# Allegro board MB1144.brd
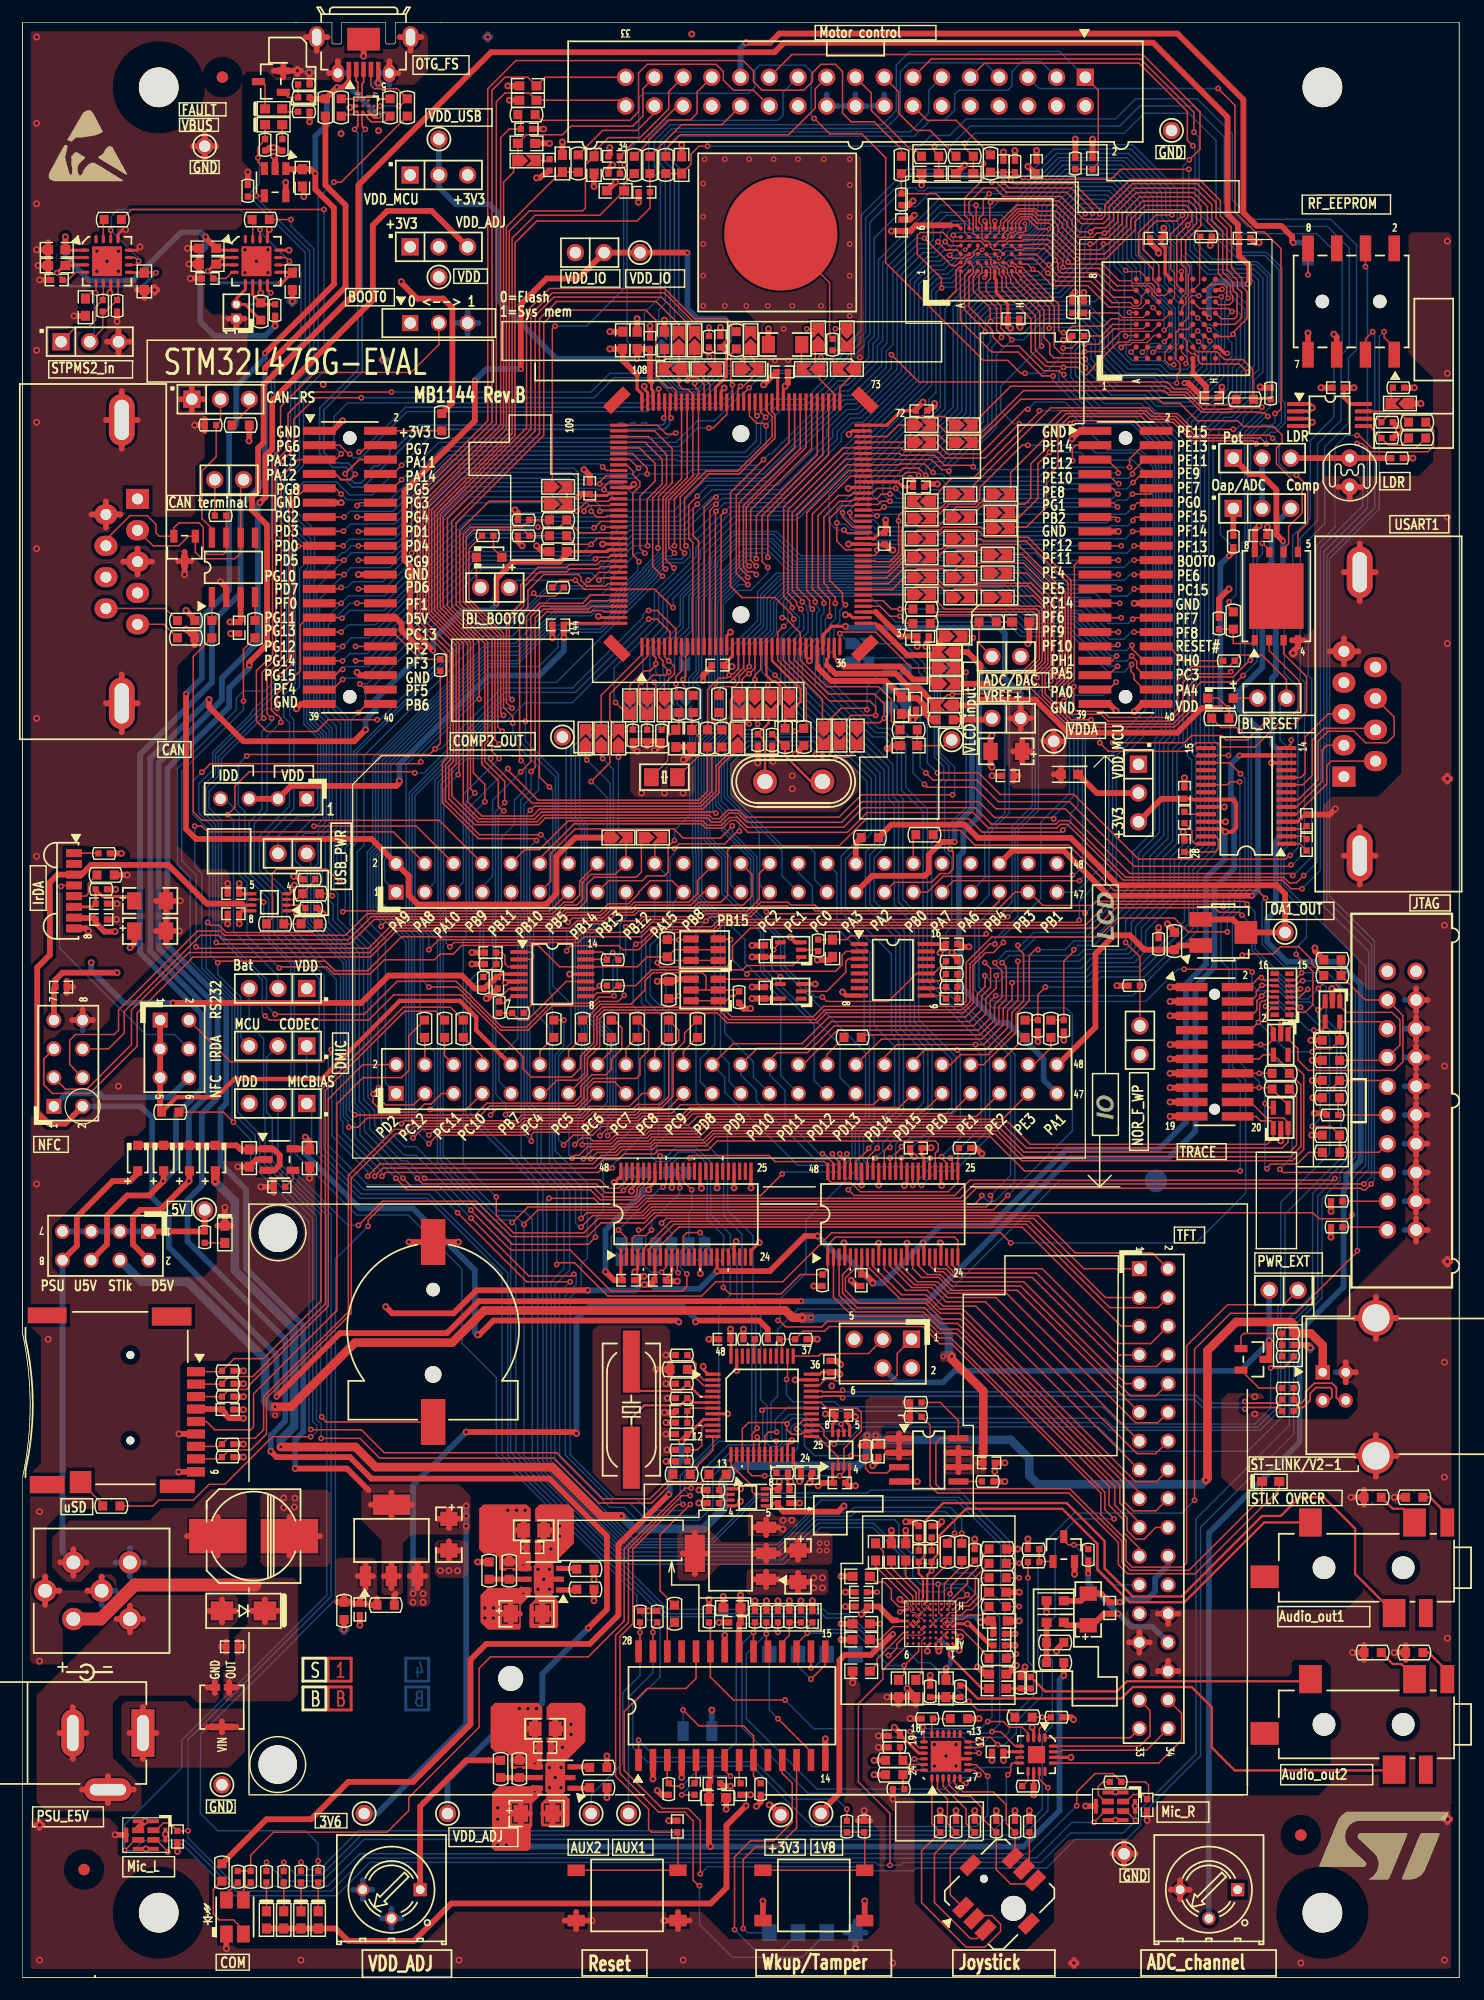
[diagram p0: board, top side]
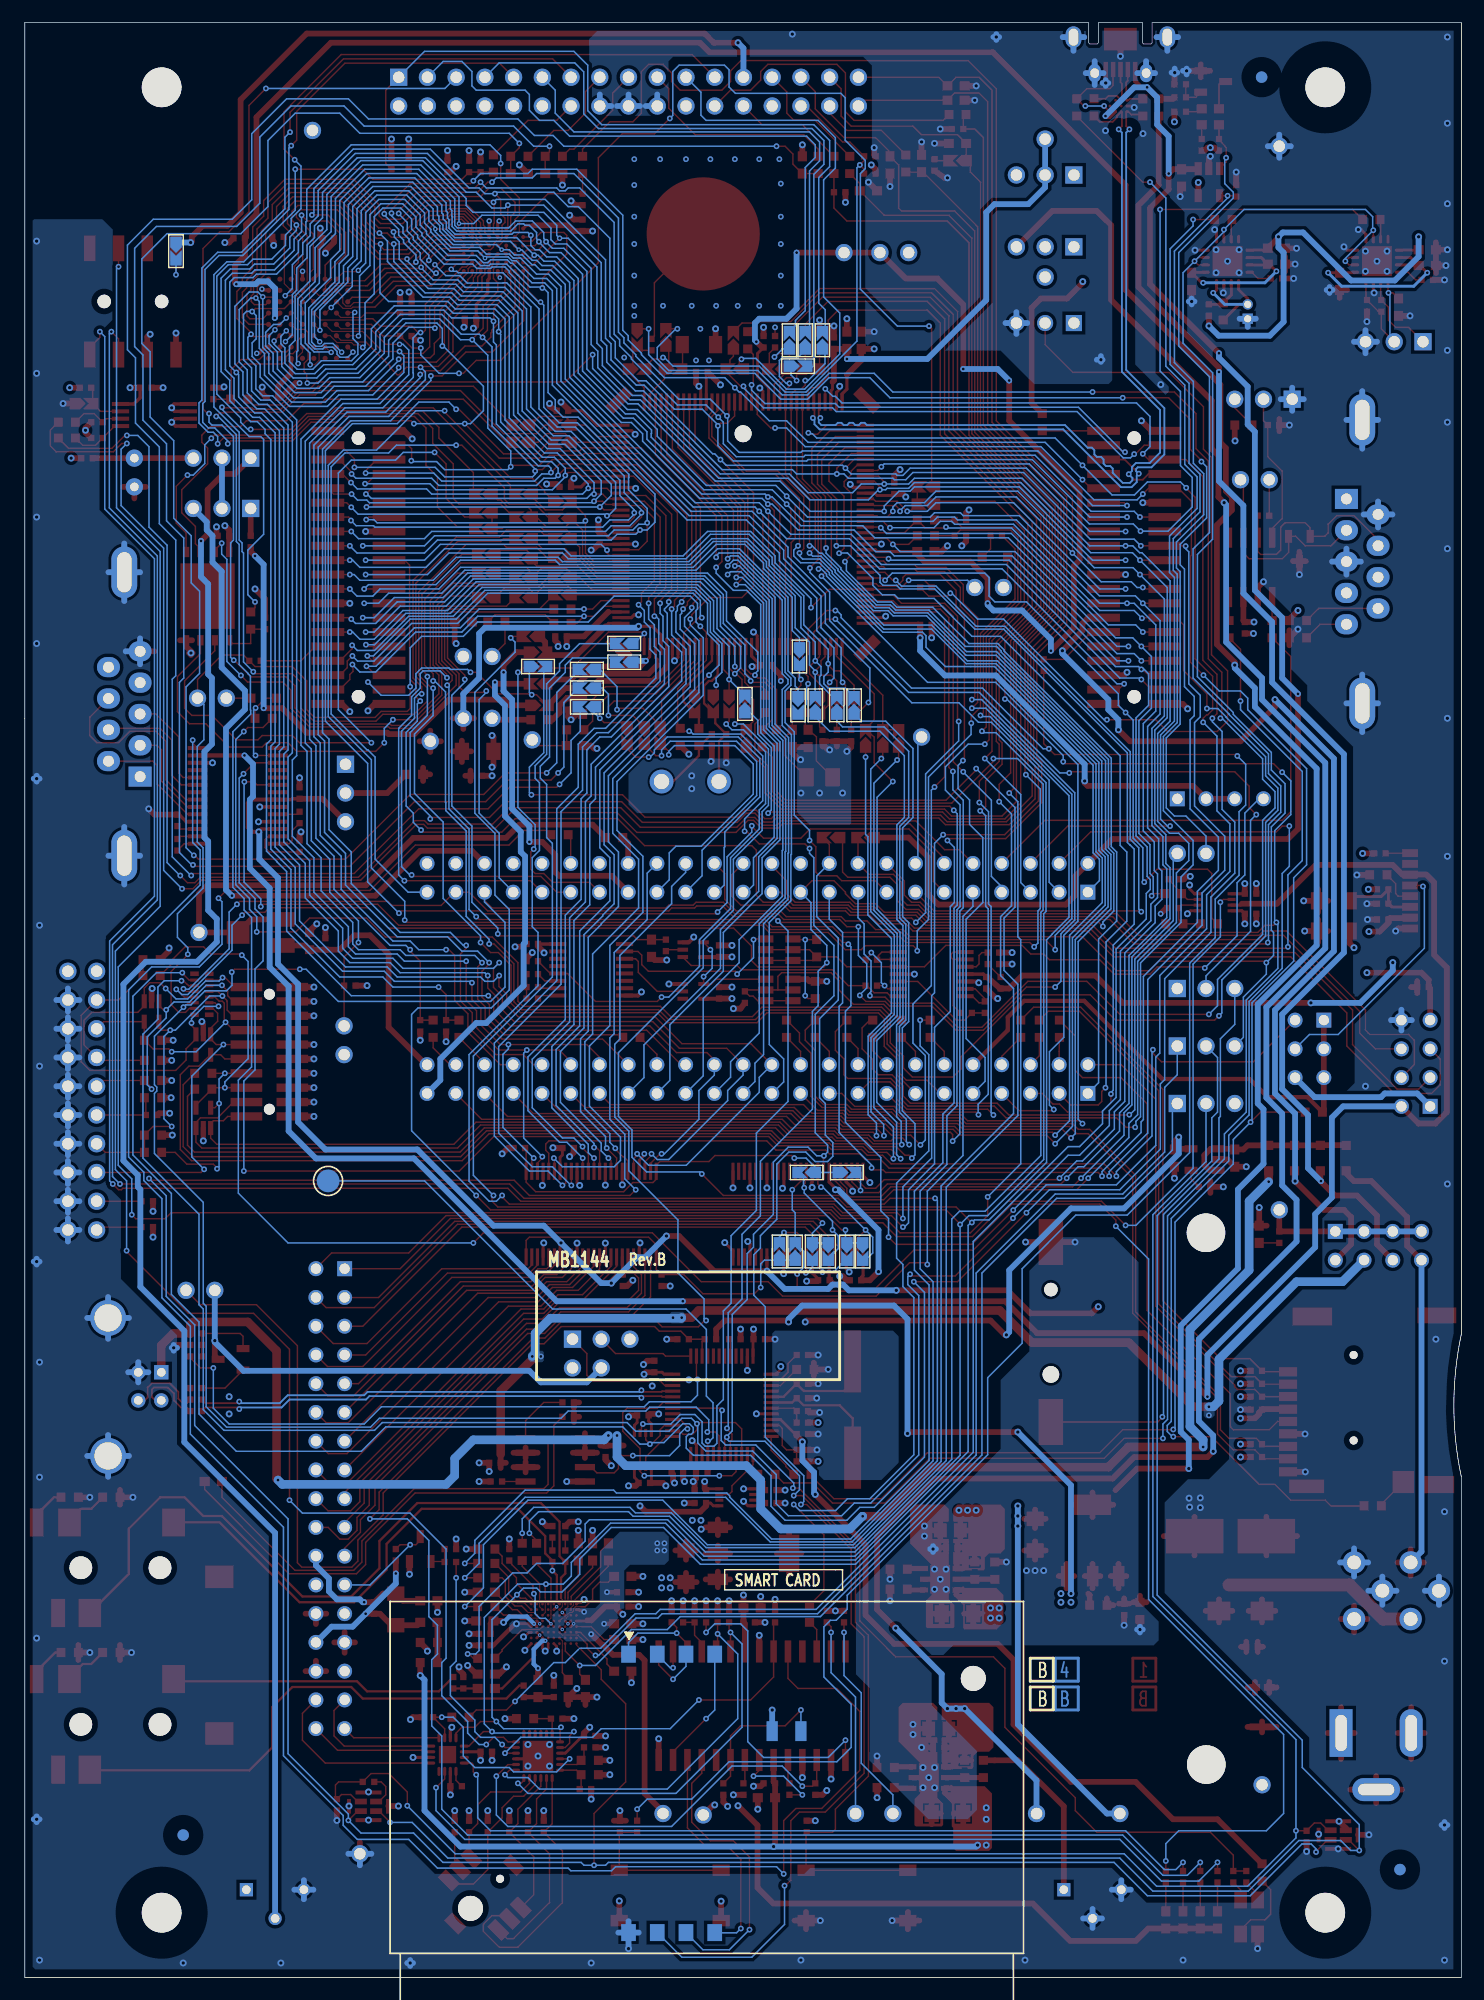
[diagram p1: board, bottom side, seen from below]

Outline 127 x 172.72 mm; copper layers: TOP, L2_VCC, L3_GND, BOTTOM. Coordinates in mm from the lower left corner of the outline.
Outline path: 0,172.72 0,56.87 ; 0,172.72 27.34,172.72 27.34,170.93 27.44,170.83 28.09,170.83 28.19,170.93 28.19,172.72 32.09,172.72 32.09,170.93 32.19,170.83 32.84,170.83 32.94,170.93 32.94,172.72 127,172.72 ; 0,172.72 0,56.87 ; 0,56.87 arc(0.67,50.53) 0,44.2 ; 0,56.87 arc(0.67,50.53) 0,44.2 ; 0,44.2 0,0 ; 0,0 127,0 ; 0,0 127,0 ; 127,0 127,111.25 ; 127,0 127,111.25 ; 127,172.72 127,111.25 ; 127,172.72 127,111.25

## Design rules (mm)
net group DIFFPAIR2: nets PA11 PA12
net group STL_USB: nets STL_USB_DM STL_USB_DP
net group ADDRESS: nets A0 A1 A2 A3 A4 A5 A6 A7 A8 A9 A10 A11 A12 A13 A14 A15 A16 A17 A18 A19 A20 A21 A22 A23
net group DATA: nets D0 D1 D2 D3 D4 D5 D6 D7 D8 D9 D10 D11 D12 D13 D14 D15

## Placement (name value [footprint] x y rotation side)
B1  RESET  [PB10]  53.44 7.24 0 top
B2  WKUP  [PB10]  69.95 7.24 0 top
B3  MT008-A  [MT-008A]  86.33 7.37 315 top
BT1  CR1220 holder  [BAT_2SM_CR1220]  36.29 57.02 90 top
C1  [N_A]  [0603C]  44.67 167.13 0 top
C2  [N_A]  [0603C]  44.67 165.86 0 top
C3  100nF  [0402C]  44.55 163.32 0 top
C4  [N_A]  [0603C]  44.55 162.05 180 top
C5  1nF  [0402C]  52.29 160.91 0 top
C6  [N_A]  [0603C]  47.72 160.27 270 top
C7  1nF  [0402C]  94.58 160.27 270 top
C8  10nF  [0402C]  46.58 160.15 270 top
C9  [N_A]  [0603C]  50.51 160.15 90 top
C10  [N_A]  [0603C]  58.26 160.15 270 top
C11  100nF  [0402C]  86.71 160.02 90 top
C12  100nF  [0402C]  89.63 160.02 90 top
C13  [N_A]  [0603C]  80.23 159.38 0 top
C14  [N_A]  [0603C]  83.28 159.38 0 top
C15  4.7uF  [0603C]  24.73 159 270 top
C16  [N_A]  [0603C]  52.42 157.86 0 top
C17  100nF  [0402C]  54.96 157.73 180 top
C18  100nF  [0402C]  77.69 154.81 90 top
C19  100nF  [0402C]  100.17 153.67 180 top
C20  100nF  [0402C]  108.05 153.67 0 top
C21  1uF  [0603C]  16.35 152.78 180 top
C22  1uF  [0603C]  3.02 152.65 180 top
C23  1uF  [0603C]  16.35 151.38 0 top
C24  1uF  [0603C]  3.02 151.26 0 top
C25  100nF  [0402C]  16.35 150.11 0 top
C26  100nF  [0402C]  3.02 149.99 0 top
C27  1uF  [0603C]  10.76 149.86 270 top
C28  1uF  [0603C]  23.84 149.86 270 top
C29  4.7uF  [0603C]  5.56 147.57 270 top
C30  100nF  [0402C]  93.82 147.57 90 top
C31  100nF  [0402C]  87.6 146.56 0 top
C32  1uF  [0603C]  53.05 144.65 90 top
C33  1uF  [0603C]  54.32 144.65 90 top
C34  220nF  [0603C]  56.74 144.65 270 top
C35  100nF  [0402C]  61.69 144.53 270 top
C36  100nF  [0402C]  55.47 144.4 270 top
C37  22nF(COG)GRM3195C1H223JA01L  [1206C]  67.41 144.27 0 top
C38  100nF  [0402C]  67.15 141.86 180 top
C39  100nF  [0402C]  116.3 140.46 0 top
C40  100nF  [0402C]  105.12 139.57 0 top
C41  100nF  [0402C]  79.47 138.43 180 top
C42  100nF  [0402C]  79.22 131.7 0 top
C43  100nF  [0402C]  50.13 131.57 270 top
C44  100nF  [0402C]  109.44 127.38 0 top
C45  100nF  [0402C]  76.17 127.13 270 top
C46  1uF  [0603C]  47.34 125.98 180 top
C47  [N_A]  [0603C]  88.23 119.76 180 top
C48  100nF  [0402C]  47.34 119.51 0 top
C49  100nF  [0402C]  19.15 119.25 90 top
C50  100nF  [0402C]  79.6 118.49 180 top
C51  100nF  [0402C]  61.44 115.95 0 top
C52  100nF  [0402C]  78.96 112.52 90 top
C53  1uF  [0603C]  77.69 112.39 270 top
C54  20pF  [0402R]  64.99 109.35 270 top
C55  20pF  [0402R]  66.26 109.35 270 top
C56  6pF  [0603C]  57.75 109.47 270 top
C57  6pF  [0603C]  59.15 109.47 270 top
C58  1uF  [0603C]  78.33 108.84 0 top
C59  1uF  [TAN-A]  86.96 108.33 0 top
C60  100nF  [0402C]  87.09 106.17 0 top
C61  100nF  [0402C]  102.71 104.65 270 top
C62  100nF  [0402C]  102.71 102.49 270 top
C63  100nF  [0402C]  113.51 102.23 90 top
C64  100nF  [0402C]  113.51 100.08 90 top
C65  100nF  [0402C]  102.71 99.95 90 top
C66  100nF  [0402C]  18.64 95.76 0 top
C67  4.7uF  [TAN-A]  11.27 95.12 180 top
C68  100nF  [0402C]  6.95 94.87 180 top
C69  100nF  [0402C]  18.64 93.98 0 top
C70  100nF  [0402C]  6.95 93.47 180 top
C71  4.7uF  [TAN-A]  11.27 92.46 180 top
C72  100nF  [0402C]  82.14 91.31 0 top
C73  1uF  [0603C]  71.6 90.93 270 top
C74  100nF  [0402C]  65.63 90.68 270 top
C75  100nF  [0402C]  42.01 87.88 270 top
C76  100nF  [0402C]  65.63 87 90 top
C77  1nF  [0402C]  82.14 86.49 0 top
C78  100nF  [0402C]  3.4 87.5 180 top
C79  100nF  [0402C]  78.96 73.28 180 top
C80  1uF  [0603C]  20.03 72.39 270 top
C81  1uF  [0603C]  25.37 72.39 270 top
C82  10nF  [0402C]  22.7 69.85 180 top
C83  100nF  [0402C]  53.56 61.59 0 top
C84  100nF  [0402C]  56.36 61.59 0 top
C85  100nF  [0402C]  74.14 61.59 270 top
C86  100nF  [0402C]  62.07 56.39 0 top
C87  100nF  [0402C]  71.34 53.98 90 top
C88  20pF  [0402R]  58.26 52.45 0 top
C89  20pF  [0402R]  58.26 51.18 0 top
C90  100nF  [0402C]  18.13 50.16 0 top
C91  100nF  [0402C]  58.26 50.04 0 top
C92  100nF  [0402C]  72.36 49.66 0 top
C93  100nF  [0402C]  58.26 48.01 0 top
C94  100nF  [0402C]  69.31 44.58 180 top
C95  100nF  [0402C]  72.23 43.69 180 top
C96  100nF  [0402C]  67.28 43.05 0 top
C97  100nF  [0402C]  67.28 41.91 0 top
C98  10uF[ESR<0.2ohm]  [0805C]  45.18 39.5 0 top
C99  10uF  [TAN-A]  37.69 39.12 90 top
C100  220uF  [C310M-6]  20.42 38.99 180 top
C101  100nF  [0402C]  45.05 37.97 0 top
C102  2.2uF  [0603C]  75.41 37.59 270 top
C103  2.2uF  [0603C]  76.8 37.59 90 top
C104  2.2uF  [0603C]  78.07 37.59 90 top
C105  100nF  [0402C]  79.22 37.21 90 top
C106  100nF  [0402C]  80.36 37.21 90 top
C107  10uF  [TAN-A]  68.55 36.32 90 top
C108  1uF  [0603C]  74.14 35.43 180 top
C109  100nF  [0402C]  74.14 34.04 180 top
C110  1uF  [0603C]  86.2 34.04 0 top
C111  100nF  [0402C]  74.14 32.77 180 top
C112  4.7uF  [0603C]  62.71 32.64 180 top
C113  100nF  [0402C]  96.11 32.64 270 top
C114  100nF  [0402C]  29.81 32.51 270 top
C115  10uF  [TAN-A]  94.2 32.51 270 top
C116  4.7uF  [TAN-A]  44.55 32.13 180 top
C117  100nF  [0402C]  69.82 31.88 270 top
C118  1uF  [0603C]  86.33 31.5 0 top
C119  100nF  [0402C]  62.96 31.37 180 top
C120  4.7uF  [0603C]  74.14 31.24 180 top
C121  100nF  [0402C]  86.33 30.35 0 top
C122  4.7uF  [0603C]  74.14 29.84 180 top
C123  100nF  [0402C]  86.33 29.34 0 top
C124  100nF  [0402C]  18.51 29.21 180 top
C125  4.7uF  [0603C]  74.14 27.05 0 top
C126  4.7uF  [0603C]  86.2 26.8 0 top
C127  4.7uF  [0603C]  77.44 25.53 90 top
C128  4.7uF  [0603C]  78.96 25.53 90 top
C129  4.7uF  [0603C]  81.63 25.53 90 top
C130  4.7uF  [0603C]  86.2 25.53 180 top
C131  10uF[ESR<0.2ohm]  [0805C]  46.2 21.97 0 top
C132  100nF  [0402C]  77.06 21.34 180 top
C133  100nF  [0402C]  46.2 20.32 0 top
C134  100nF  [0402C]  86.2 19.94 180 top
C135  100nF  [0402C]  61.18 17.14 0 top
C136  100nF  [0402C]  59.4 16.64 90 top
C137  100nF  [0402C]  63.47 16.64 270 top
C138  4.7uF  [0603C]  61.44 15.88 0 top
C139  100nF  [0402C]  99.41 15.24 270 top
C140  4.7uF  [TAN-A]  45.43 14.48 180 top
C141  100nF  [0402C]  57.88 13.34 270 top
C142  100nF  [0402C]  13.68 12.45 270 top
C143  100nF  [0402C]  85.44 45.47 180 top
C144  100nF  [0402C]  41.37 90.55 180 top
C145  100nF  [0402C]  75.66 46.48 270 top
CN1  475900001  [MOLEX_47590001]  30.14 168.58 180 top
CN2  MC_connector  [IDC34S]  93.95 167.89 270 top
CN3  F206A-2_04MGF-A  [SSM-104-L-DH]  117.44 148.08 0 top
CN4  Header 3X1  [SIP3]  3.4 144.53 0 top
CN5  DB9-male  [DB9_M]  10.16 125.09 90 top
CN6  P1039-2_20MGF-089-1A  [FTR-120-53-L-D-LC]  28.92 124.59 270 top
CN7  P1039-2_20MGF-089-1A  [FTR-120-53-L-D-LC]  97.5 124.59 270 top
CN8  Header 2X1  [SIP2]  88.23 116.71 180 top
CN9  DB9-male  [DB9_M]  116.81 111.63 270 top
CN10  -  [SIP2]  85.69 111.25 0 top
CN11  Header 24X2  [HDR_2X24_2R54]  33.02 95.89 0 top
CN12  -  [FTSH-110-01-L-DV]  105.38 81.79 270 top
CN13  female conn 4X2  [HDR_2X4_2R54_N]  2.76 76.96 90 top
CN14  Header 24X2  [HDR_2X24_2R54]  33.02 78.11 0 top
CN15  JTAG  [IDC20S]  120.65 88.9 0 top
CN16  [N_A]  [HDR_2X3-1_2R54-6]  78.58 56.39 180 top
CN17  USB-typeB connector  [USB-B]  114.94 53.47 90 top
CN18  PJS008-2000 (SMS064FF or SMS128FF)  [MSD_PJS008_]  9.53 54.99 270 top
CN19  16-bit connector  [HDR_2X17_2R54]  98.72 62.62 270 top
CN20  PJ3028B-3  [PJ3028B]  122.05 36.2 180 top
CN21  PJ3028B-3  [PJ3028B]  122.05 22.35 180 top
CN22  DC-10B  [PWR_JACK_DC10]  10.64 21.59 0 top
CN23  C816  [SAM_C816]  69.82 16.26 270 bottom
D1  EMIF02-USB03F2  [BGA11_0R5_1R57X2R07]  30.32 165.35 270 top
D2  ESDCAN24-2BLY  [SOT23-213]  14.32 126.24 180 top
D3  BAT60JFILM  [SOD-323]  41.24 125.48 180 top
D4  BAT60JFILM  [SOD-323]  105.89 113.03 180 top
D5  BAT60JFILM  [SOD-323]  10.18 72.39 90 top
D6  BAT60JFILM  [SOD-323]  12.47 72.39 90 top
D7  BAT60JFILM  [SOD-323]  14.75 72.39 90 top
D8  BAT60JFILM  [SOD-323]  17.04 72.39 90 top
JP1  -  [SIP3]  34.26 159.26 0 top
JP2  -  [SIP3]  34.26 152.91 0 top
JP3  -  [SIP2]  48.86 152.4 0 top
JP4  -  [SIP3]  14.95 139.45 0 top
JP5  -  [SIP3]  107.03 134.24 0 top
JP6  -  [SIP2]  16.99 132.33 0 top
JP7  -  [SIP3]  107.03 129.79 0 top
JP8  -  [SIP2]  43.02 122.81 180 top
JP9  -  [SIP2]  111.73 113.03 180 top
JP10  -  [SIP3]  98.65 107.19 270 top
JP11  Header 4  [SIP4]  25.11 104.14 180 top
JP12  -  [SIP3]  25.11 87.38 180 top
JP13  -  [SIP2]  98.77 81.53 90 top
JP14  -  [SIP3]  25.11 82.3 180 top
JP15  Header 3X2  [HDR_2X3_2R54]  12.16 84.58 270 top
JP16  -  [SIP3]  25.11 77.22 180 top
JP17  Header 4X2  [HDR_2X4_2R54]  11.14 65.91 180 top
JP18  -  [SIP2]  110.2 60.71 0 top
JP19  -  [SIP2]  25.11 99.31 180 top
L1  BEAD  [0603L]  92.55 106.3 180 top
L2  BNX002-01  [BNX001]  6.98 34.16 180 top
L3  BEAD  [0603L]  91.28 33.27 180 top
L4  BEAD  [0603L]  91.28 31.37 180 top
LD1  Green  [0603D]  26.13 5.08 90 top
LD2  Orange  [0603D]  24.61 5.08 90 top
LD3  Red  [0603D]  23.08 5.08 90 top
LD4  Blue  [0603D]  21.56 5.08 90 top
LD5  Green  [0603D]  22.19 165.1 180 top
LD6  Red  [0603D]  22.19 163.7 180 top
LD7  Red  [0603D]  17.88 65.66 90 top
LD8  HSMF-A201-A00J1  [LED2_3528]  18.76 5.33 0 top
LD9  Red  [0603D]  110.33 43.81 180 top
NOREF  -  [unnamed]  12.03 5.71 0 top
NOREF#2  -  [#2]  239.8 163.12 0 top
NOREF#3  -  [#2]  6.32 0 0 top
NOREF#4  -  [unnamed]  5.43 9.53 0 top
NOREF#5  -  [#2]  12.67 209.55 0 top
NOREF#6  -  [#2]  139.03 -25.03 90 top
NOREF#7  -  [#2]  0 172.72 0 top
NOREF#8  -  [unnamed]  114.9 167 0 top
NOREF#9  -  [unnamed]  12.03 167 0 top
NOREF#10  -  [unnamed]  113 12.57 0 top
NOREF#11  -  [unnamed]  114.9 5.71 0 top
NOREF#12  -  [#2]  5.81 -7.11 0 top
NOREF#13  -  [#2]  141.57 -25.03 90 top
NOREF#14  -  [#2]  402.05 -43.74 0 top
NOREF#15  -  [#2]  127 0 90 top
NOREF#16  -  [unnamed]  17.66 167.9 0 top
NOREF#17  -  [#2]  176.5 202.69 0 top
NOREF#18  -  [unnamed]  113 12.57 180 bottom
NOREF#19  -  [unnamed]  5.43 9.53 180 bottom
NOREF#20  -  [unnamed]  17.66 167.9 180 bottom
NOREF#21  -  [unnamed]  22.58 65.79 180 bottom
NOREF#22  -  [unnamed]  22.55 18.8 180 bottom
R1  47K  [0402R]  24.86 166.12 180 top
R2  0  [0603R]  26.77 165.23 90 top
R3  0  [0603R]  28.16 165.23 270 top
R4  0  [0603R]  32.48 165.23 270 top
R5  0  [0603R]  34 165.23 270 top
R6  330  [0402R]  24.86 164.85 180 top
R7  0  [0603R]  44.55 164.59 180 top
R8  47K  [0402R]  21.43 161.93 90 top
R9  620  [0402R]  22.96 161.93 90 top
R10  0  [0603R]  80.23 160.91 180 top
R11  0  [0603R]  83.28 160.91 180 top
R12  0  [0603R]  49.12 160.27 270 top
R13  0  [0603R]  85.57 160.27 270 top
R14  3K3  [0402R]  93.06 160.27 90 top
R15  0  [0603R]  54.07 160.15 90 top
R16  0  [0603R]  55.47 160.15 270 top
R17  0  [0603R]  56.86 160.15 90 top
R18  0  [0603R]  77.69 160.15 90 top
R19  100K  [0402R]  87.73 160.02 90 top
R20  3K3  [0402R]  52.29 159.38 180 top
R21  10K  [0402R]  19.91 157.86 270 top
R22  10K  [0402R]  77.69 157.1 90 top
R23  0  [0603R]  7.97 155.32 180 top
R24  0  [0603R]  21.05 155.32 180 top
R25  10K  [0402R]  104.62 153.8 180 top
R26  1K  [0402R]  7.08 147.7 270 top
R27  1K  [0402R]  8.35 147.7 270 top
R28  10K  [0402R]  92.81 147.57 270 top
R29  3K3  [0402R]  22.32 147.32 90 top
R30  PT100  [HDR_1X2_1R27]  18.89 146.56 90 top
R31  100 1%  [0603R]  21.05 147.19 270 top
R32  10K  [0402R]  93.31 145.03 0 top
R33  0  [SB_0603]  58.01 144.65 270 top
R34  0  [0603R]  63.09 144.65 270 top
R35  0  [SB_0603]  64.36 144.65 270 top
R36  0  [SB_0603]  59.4 144.65 270 top
R37  1K  [0402R]  60.67 144.53 90 top
R38  0  [SB_0603]  70.33 144.91 270 top
R39  0  [SB_0603]  72.87 144.91 90 top
R40  10K  [0402R]  71.6 144.27 90 top
R41  10K  [0402R]  110.33 139.95 270 top
R42  10K  [0402R]  121.63 140.46 180 top
R43  0  [0603R]  108.05 139.45 180 top
R44  0  [0603R]  37.05 137.41 270 top
R45  10K  [0402R]  16.61 137.16 180 top
R46  0  [0603R]  19.27 137.16 0 top
R48  0  [SB_0603]  79.47 137.16 180 top
R50  0  [SB_0603]  79.47 135.64 180 top
R51  8.2K  [0402R]  121.51 134.24 0 top
R52  VT9ON1  [PVT901]  117.32 132.97 180 top
R53  0  [SB_0603]  47.34 130.18 180 top
R54  0  [SB_0603]  79.47 130.43 0 top
R55  120  [0402R]  17.49 129.16 180 top
R56  0  [SB_0603]  79.47 128.91 180 top
R57  1K2  [0402R]  44.29 128.78 180 top
R58  0  [0603R]  47.34 128.78 0 top
R59  150  [0402R]  41.12 127.38 180 top
R60  1K2  [0402R]  44.29 127.38 180 top
R61  0  [0603R]  47.34 127.38 0 top
R62  0  [SB_0603]  79.47 127.13 180 top
R63  1K  [0402R]  107.03 126.87 270 top
R64  0  [SB_0603]  79.47 125.48 180 top
R65  0  [SB_0603]  82.9 125.35 180 top
R66  0  [SB_0603]  79.47 123.7 180 top
R67  10K  [0402R]  47.34 122.81 0 top
R68  0  [SB_0603]  79.47 122.17 180 top
R69  0  [0603R]  79.47 120.9 0 top
R70  [N_A]  [0603R]  14.45 119.89 180 top
R71  0  [0603R]  107.03 119.89 90 top
R72  0  [0603R]  85.31 119.76 180 top
R73  0  [0603R]  79.47 119.63 0 top
R74  10K  [0402R]  105.76 119.63 270 top
R75  0  [0603R]  16.73 119.13 270 top
R76  0  [0603R]  20.54 119.13 90 top
R77  0  [0603R]  14.45 118.36 180 top
R78  0  [SB_0603]  81.63 117.09 0 top
R79  820  [0402R]  106.65 116.33 180 top
R80  820  [0402R]  36.93 115.95 270 top
R81  0  [SB_0603]  81.63 115.7 180 top
R82  0  [SB_0603]  81.63 114.3 180 top
R83  0  [SB_0603]  81.5 112.39 0 top
R84  0  [SB_0603]  53.69 112.39 90 top
R85  0  [SB_0603]  55.21 112.39 90 top
R86  0  [SB_0603]  56.74 112.39 90 top
R87  0  [0603R]  58.01 112.52 90 top
R88  0  [0603R]  59.28 112.52 90 top
R89  0  [0603R]  61.56 112.52 90 top
R90  0  [SB_0603]  63.34 112.52 90 top
R91  0  [SB_0603]  64.74 112.52 90 top
R92  0  [0603R]  81.5 111.12 180 top
R93  0  [0603R]  105.89 111.25 180 top
R94  0  [0603R]  78.33 110.24 0 top
R95  390  [0603R]  67.41 109.6 270 top
R96  [N_A]  [0603R]  69.06 109.6 270 top
R97  0  [SB_0603]  70.83 109.73 90 top
R98  0  [SB_0603]  72.23 109.73 90 top
R99  0  [SB_0603]  73.76 109.73 90 top
R100  100K  [0402R]  53.94 109.73 270 top
R101  100K  [0402R]  55.21 109.73 270 top
R102  100K  [0402R]  56.48 109.73 270 top
R103  0  [SB_0603]  51.15 109.47 270 top
R104  0  [SB_0603]  52.67 109.47 270 top
R105  0  [0603R]  60.55 109.47 90 top
R106  0  [0603R]  61.82 109.47 90 top
R107  0  [0603R]  79.72 100.97 180 top
R108  0  [SB_0603]  52.67 100.71 180 top
R109  0  [SB_0603]  55.72 100.71 180 top
R110  100K  [0402R]  78.96 50.8 0 top
R111  0  [0603R]  74.9 100.71 180 top
R112  5.1  [0402R]  7.21 99.31 180 top
R113  0  [0603R]  7.33 97.41 0 top
R114  100K  [0402R]  25.37 97.03 180 top
R115  47  [0402R]  6.95 96.14 180 top
R116  0  [0603R]  25.5 95.76 0 top
R117  100K  [0402R]  25.5 94.49 0 top
R118  0  [0603R]  22.32 93.09 180 top
R119  [N_A]  [0603R]  25.37 93.09 0 top
R120  [N_A]  [0603R]  101.82 91.57 90 top
R121  1K  [0402R]  100.43 91.31 270 top
R122  10K  [0402R]  70.33 91.19 90 top
R123  1K[1%]  [0603R]  56.99 90.93 90 top
R124  1K  [0402R]  41.37 89.53 180 top
R125  3K6 0.1%  [0402R]  52.17 89.92 0 top
R126  [N_A]  [0603R]  115.79 89.92 180 top
R127  220K  [0402R]  82.14 89.79 180 top
R128  22K  [0402R]  40.74 87.88 90 top
R129  180K 0.1%  [0402R]  43.78 85.22 0 top
R130  30K  [0402R]  82.14 88.65 0 top
R131  [N_A]  [0603R]  115.79 88.52 0 top
R132  180K 0.1%  [0402R]  52.17 87.63 0 top
R133  10K  [0402R]  98.27 87.63 0 top
R134  15K  [0402R]  82.14 87.5 0 top
R135  1[1%]  [0603R]  57.12 87.25 90 top
R136  3K6 0.1%  [0402R]  42.13 85.72 270 top
R137  220K  [0402R]  63.34 86.61 270 top
R138  100K  [0402R]  89.76 84.07 270 top
R139  100K  [0402R]  92.04 84.07 270 top
R140  0  [0603R]  35.53 83.82 270 top
R141  0  [0603R]  37.31 83.82 270 top
R142  0  [0603R]  38.96 83.82 270 top
R143  0  [0603R]  46.96 83.82 270 top
R144  0  [0603R]  49.5 83.82 270 top
R145  0  [0603R]  52.04 83.82 270 top
R146  0  [0603R]  54.32 83.82 270 top
R147  0  [0603R]  57.12 83.82 270 top
R148  0  [0603R]  59.66 83.82 270 top
R149  0  [0603R]  88.61 83.82 270 top
R150  0  [0603R]  90.9 83.82 270 top
R151  0  [0603R]  73.37 83.06 180 top
R152  [N_A]  [0603R]  115.67 82.8 180 top
R153  [N_A]  [0603R]  115.67 81.03 180 top
R154  0  [0603R]  111.22 79.88 0 top
R155  [N_A]  [0603R]  115.67 79.25 0 top
R156  0  [0603R]  111.22 78.49 0 top
R157  [N_A]  [0603R]  115.67 77.72 180 top
R158  [N_A]  [0603R]  13.05 76.45 0 top
R159  10K  [0402R]  115.79 76.2 0 top
R160  [N_A]  [0603R]  115.67 74.42 180 top
R161  10K  [0402R]  83.28 73.28 180 top
R162  [N_A]  [0603R]  115.67 72.9 0 top
R163  10K  [0402R]  116.17 68.58 0 top
R164  10K  [0402R]  116.17 66.29 0 top
R165  1K  [0402R]  16.1 65.41 90 top
R166  10K  [0402R]  70.71 61.59 90 top
R167  10K  [0402R]  111.86 56.9 180 top
R168  100K  [0402R]  64.23 56.39 180 top
R169  2K2  [0402R]  66.39 56.39 180 top
R170  4K7  [0402R]  68.8 56.39 180 top
R171  36K  [0402R]  111.86 55.88 0 top
R172  10K  [0402R]  58.26 54.99 0 top
R173  100  [0402R]  111.86 54.86 180 top
R174  [N_A]  [0603R]  58.01 53.72 0 top
R175  47K  [0402R]  18.13 53.59 180 top
R176  47K  [0402R]  18.13 52.45 180 top
R177  1.5K  [0402R]  111.86 52.07 0 top
R178  47K  [0402R]  18.13 51.31 180 top
R179  22  [0402R]  111.86 51.05 0 top
R180  22  [0402R]  111.86 50.04 0 top
R181  100K  [0402R]  58.26 49.02 180 top
R182  47K  [0402R]  18.13 47.12 180 top
R183  4K7  [0402R]  58.26 46.61 180 top
R184  2K2  [0402R]  85.31 43.81 0 top
R185  47K  [0402R]  18.13 45.97 180 top
R186  4K7  [0402R]  58.26 45.59 0 top
R187  100K  [0402R]  67.15 44.58 0 top
R188  0  [0603R]  58.26 44.45 180 top
R189  0  [0603R]  61.44 44.45 0 top
R190  100K  [0402R]  61.06 43.05 0 top
R191  0  [0603R]  119.35 42.42 180 top
R192  0  [0603R]  123.03 42.42 0 top
R193  100K  [0402R]  61.06 41.91 0 top
R194  0  [0603R]  7.84 41.66 180 top
R195  20  [0402R]  79.22 39.37 90 top
R196  20  [0402R]  80.36 39.37 90 top
R197  [N_A]  [0603R]  86.2 37.85 180 top
R198  0  [0603R]  81.76 37.59 90 top
R199  0  [0603R]  83.03 37.59 90 top
R200  10K  [0402R]  84.17 37.34 90 top
R201  0  [0603R]  86.2 36.58 0 top
R202  [N_A]  [0603R]  49.75 36.07 180 top
R203  11.8K[1%]  [0603R]  41.24 35.94 90 top
R204  20.5K[1%]  [0603R]  43.02 35.94 270 top
R205  0  [0603R]  86.2 35.31 0 top
R206  [N_A]  [0603R]  49.75 34.29 0 top
R207  124[1%]  [0603R]  32.1 32.89 0 top
R208  0  [0603R]  86.2 32.77 0 top
R209  232[1%]  [0603R]  28.42 32.38 90 top
R210  0  [0603R]  57.63 32.13 90 top
R211  10K  [0402R]  54.58 31.88 270 top
R212  10K  [0402R]  56.1 31.88 270 top
R213  100K  [0402R]  60.67 31.88 90 top
R214  100K  [0402R]  64.74 31.88 270 top
R215  100K  [0402R]  65.75 31.88 270 top
R216  4K7  [0402R]  66.77 31.88 270 top
R217  10K  [0402R]  67.79 31.88 270 top
R218  10K  [0402R]  68.8 31.88 90 top
R219  [N_A]  [0603R]  91.28 29.59 180 top
R220  0  [0603R]  119.35 28.7 180 top
R221  0  [0603R]  123.03 28.7 180 top
R222  0  [0603R]  86.2 28.19 180 top
R223  0  [0603R]  91.28 27.81 180 top
R224  1K  [0402R]  88.23 26.04 270 top
R225  180  [0402R]  89.12 26.04 90 top
R226  1K  [0402R]  80.23 25.27 270 top
R227  180  [0402R]  82.9 25.27 270 top
R228  0  [0603R]  88.49 22.99 0 top
R229  100K  [0402R]  91.41 22.99 180 top
R230  10K  [0402R]  79.98 22.86 0 top
R231  [N_A]  [0603R]  82.77 22.86 180 top
R232  10K  [0402R]  77.06 20.32 0 top
R233  [N_A]  [0603R]  77.06 19.18 0 top
R234  [N_A]  [0603R]  50.9 18.54 180 top
R235  10.2K[1%]  [0603R]  42.26 18.41 90 top
R236  20K[1%]  [0603R]  43.91 18.41 270 top
R237  [N_A]  [0603R]  77.06 17.91 0 top
R238  10K  [0402R]  96.62 17.27 0 top
R239  100K  [0402R]  88.87 16.89 0 top
R240  [N_A]  [0603R]  50.9 16.76 0 top
R241  100K  [0402R]  57.12 16.64 270 top
R242  100K  [0402R]  65.25 16.64 90 top
R243  10K  [0402R]  77.44 16.64 0 top
R244  330  [0402R]  72.87 13.34 90 top
R245  220K  [0402R]  74.39 13.34 90 top
R246  10K  [0402R]  81.12 13.34 270 top
R247  10K  [0402R]  82.52 13.34 90 top
R248  10K  [0402R]  84.17 13.34 90 top
R249  10K  [0402R]  86.07 13.34 90 top
R250  10K  [0402R]  87.73 13.34 90 top
R251  100  [0402R]  89 13.34 270 top
R252  0  [0603R]  17.62 9.27 90 top
R253  100  [0402R]  19.02 8.89 270 top
R254  100  [0402R]  20.16 8.89 270 top
R255  680  [0402R]  21.56 8.89 270 top
R256  680  [0402R]  23.08 8.89 270 top
R257  680  [0402R]  24.61 8.89 270 top
R258  510  [0402R]  26.13 8.89 270 top
R259  47K  [0402R]  94.2 37.34 90 top
R260  1K  [0402R]  89.38 36.7 0 top
R261  22K  [0402R]  24.86 167.26 180 top
R262  10K  [0402R]  74.52 46.48 90 top
R263  1K2  [0402R]  120.62 136.02 180 top
R264  1K2  [0402R]  120.62 137.41 180 top
R265  0  [0603R]  123.29 136.02 0 top
R266  0  [0603R]  123.29 137.41 0 top
R267  22K  [0402R]  89.38 37.85 180 top
R268  1K  [0402R]  78.96 49.53 0 top
RS1  22  [RP0402X8_REV]  111.22 87 90 top
RV1  3386P-503H[5%]  [3386P]  32.61 7.75 180 top
RV2  3314J-1-103  [PTF_3314J]  106.14 92.33 270 top
RV3  3386P-103(10K)  [3386P]  104.87 7.75 180 top
SB1  Open by default  [SB_0603]  44.55 160.53 180 top
SB2  Open by default  [SB_0603]  60.55 142.11 180 top
SB3  Open by default  [SB_0603]  72.87 142.11 0 top
SB4  Open by default  [SB_0603]  57.5 142.11 0 top
SB5  Open by default  [SB_0603]  64.23 142.11 180 top
SB6  Open by default  [SB_0603]  69.69 142.11 0 top
SB7  Closed by default  [SB_0603]  121.76 139.06 0 top
SB8  Open by default  [SB_0603]  83.15 137.16 180 top
SB9  Open by default  [SB_0603]  83.15 135.64 180 top
SB10  Open by default  [SB_0603]  47.34 131.7 180 top
SB11  Open by default  [SB_0603]  82.9 131.06 180 top
SB12  Open by default  [SB_0603]  86.46 131.06 180 top
SB13  Open by default  [SB_0603]  82.9 129.03 180 top
SB14  Open by default  [SB_0603]  86.46 129.41 180 top
SB15  Open by default  [SB_0603]  86.46 128.02 180 top
SB16  Open by default  [SB_0603]  82.9 127.13 180 top
SB17  Open by default  [SB_0603]  86.2 125.73 180 top
SB18  Open by default  [SB_0603]  86.2 124.08 180 top
SB19  Open by default  [SB_0603]  82.9 123.7 180 top
SB20  Open by default  [SB_0603]  86.2 121.92 180 top
SB21  Open by default  [SB_0603]  82.9 121.92 180 top
SB22  Open by default  [SB_0603]  82.26 118.49 180 top
SB23  Open by default  [SB_0603]  67.79 112.52 90 top
SB24  Open by default  [SB_0603]  66.14 112.52 90 top
SB25  Open by default  [SB_0603]  63.21 109.47 270 top
SB26  Open by default  [SB_0603]  49.75 109.47 270 top
SB27  Open by default  [SB_0603]  59.4 144.65 270 bottom
SB28  Open by default  [SB_0603]  58.01 144.65 270 bottom
SB29  Open by default  [SB_0603]  56.48 144.65 270 bottom
SB30  Open by default  [SB_0603]  58.64 142.37 0 bottom
SB31  Open by default  [SB_0603]  74.01 117.86 180 bottom
SB32  Open by default  [SB_0603]  74.01 116.2 180 bottom
SB33  Open by default  [SB_0603]  58.52 116.71 90 bottom
SB34  Open by default  [SB_0603]  77.31 115.57 180 bottom
SB35  Open by default  [SB_0603]  81.63 115.82 0 bottom
SB36  Open by default  [SB_0603]  77.31 113.92 180 bottom
SB37  Open by default  [SB_0603]  63.34 112.52 270 bottom
SB38  Open by default  [SB_0603]  57.12 112.39 270 bottom
SB39  Open by default  [SB_0603]  55.21 112.39 270 bottom
SB40  Open by default  [SB_0603]  53.69 112.39 270 bottom
SB41  Open by default  [SB_0603]  58.64 112.39 90 bottom
SB42  Open by default  [SB_0603]  77.31 112.27 180 bottom
SB43  Open by default  [SB_0603]  113.63 152.53 90 bottom
SB44  Open by default  [SB_0603]  52.93 64.14 90 bottom
SB45  Closed by default  [SB_0603]  54.32 64.14 90 bottom
SB46  Open by default  [SB_0603]  55.98 64.14 90 bottom
SB47  Closed by default  [SB_0603]  57.37 64.14 90 bottom
SB48  Closed by default  [SB_0603]  57.88 71.12 180 bottom
SB49  Open by default  [SB_0603]  54.32 71.12 0 bottom
SB50  Closed by default  [SB_0603]  60.29 64.14 270 bottom
SB51  Open by default  [SB_0603]  58.9 64.14 270 bottom
SW1  09.03290.01  [SW1_3TH_2R54_10X2R5]  34.26 146.18 0 top
T1  9013-SOT23  [SOT-23]  21.94 167.51 90 top
T2  FDC606P  [SOT23-6]  60.29 90.81 90 top
T3  FDC606P  [SOT23-6]  60.29 87.25 90 top
T4  9013-SOT23  [SOT-23]  108.81 54.61 270 top
T6  9013-SOT23  [SOT-23]  92.04 37.85 0 top
TP1  [N_A]  [TP]  101.57 163.19 180 top
TP2  [N_A]  [TP]  36.8 162.43 0 top
TP3  [N_A]  [TP]  16.1 161.8 270 top
TP4  [N_A]  [TP]  54.58 152.4 0 top
TP5  [N_A]  [TP]  36.8 150.24 0 top
TP6  [N_A]  [TP]  47.72 109.6 180 top
TP7  [N_A]  [TP]  82.14 109.35 0 top
TP8  [N_A]  [TP]  91.15 109.22 90 top
TP9  [N_A]  [TP]  111.6 92.33 270 top
TP10  [N_A]  [TP]  16.1 67.82 180 top
TP11  [N_A]  [TP]  17.62 17.02 180 top
TP12  [N_A]  [TP]  30.19 14.48 90 top
TP13  [N_A]  [TP]  37.56 14.48 180 top
TP14  [N_A]  [TP]  50.26 14.48 0 top
TP15  [N_A]  [TP]  53.56 14.48 0 top
TP16  [N_A]  [TP]  70.58 14.48 180 top
TP17  [N_A]  [TP]  67.02 14.35 180 top
TP18  [N_A]  [TP]  97.38 10.92 0 top
TP19  [N_A]  [TP_C79]  100.19 70.37 180 bottom
TS1  -  [TS_PAD]  67.02 154.05 0 top
U1  STMPS2151STR  [SOT23-5]  22.32 158.62 180 top
U2  IS61WV102416BLL-10MLI  [BGA48_0R75_9X11]  85.57 152.65 90 top
U3  STPMS2L-PUR  [QFN16_0R65_4X4]  7.46 151.64 0 top
U4  STPMS2L-PUR  [QFN16_0R65_4X4]  20.67 151.64 0 top
U5  M29W128GL70ZA6E  [BGA64_1_10X13]  101.95 146.56 90 top
U6  M24128-DFDW6TP  [TSSOP8_0R65_3X6R4]  115.54 138.05 270 top
U7  STM32L476ZGT6U  [TQFP144_0R5_22X22_SOCKET]  63.5 128.4 90 top
U8  SN65HVD230  [SOIC8_1R27_4R9X6]  18.64 124.59 0 top
U9  N25Q256A13EF840E  [DFN8_1R27_6X8_TP4R8X5R8]  110.84 122.05 0 top
U10  ST3241EBPR  [SSOP28_0R65_10R2X7R8]  108.17 104.39 90 top
U11  TFDU6300  [IR_VISHAY3]  4.54 96.01 90 top
U12  SN74LVC2T45DCUT  [USOP8_0R5_2X3R1]  21.81 95 90 top
U13  SN74LVC1G66DCKT  [SC70-5]  67.91 90.81 90 top
U14  74LV4060PW  [TSSOP16_0R65_5X6R4]  76.93 89.03 270 top
U15  TSZ124IPT  [TSSOP14_0R65_5X6R4]  46.83 88.65 270 top
U16  SN74LVC1G04DCKT  [SC70-5]  67.91 87.12 90 top
U17  ESDALC6V1W5  [SOT-353]  115.79 85.34 180 top
U18  ESDALC6V1W5  [SOT-353]  111.22 82.42 180 top
U19  ESDALC6V1W5  [SOT-353]  111.22 75.95 0 top
U20  LD3985M33R  [SOT23-5]  22.7 72.26 270 top
U21  SN74LVC16T245DGGR  [TSSOP48_0R5_12R5X8R1]  58.64 67.44 0 top
U22  SN74LVC16T245DGGR  [TSSOP48_0R5_12R5X8R1]  76.93 67.44 0 top
U23  STM32F103CBT6  [LQFP48_0R5_9X9]  65.37 50.55 0 top
U24  SN74LVC2T45DCUT  [USOP8_0R5_2X3R1]  72.36 46.61 0 top
U25  SN74LVC2T45DCUT  [USOP8_0R5_2X3R1]  64.1 42.42 270 top
U26  LD1117STR  [SOT-223]  32.61 38.61 0 top
U27  LD1117S18TR  [SOT-223]  62.58 37.47 90 top
U28  ST1L05BPUR  [DFN6_0R95_3X3]  46.07 35.18 90 top
U29  WM8994ECS_R  [BGA72_0R5_4R5X4]  80.23 31.24 180 top
U30  ST8024CDR  [SOIC28W_1R27_17R9X10R325]  62.71 24 0 top
U31  ZEN056V130A24LS  [TYCO_ZEN056V130A24LS]  17.62 23.88 90 top
U32  STMPE811QTR  [QFN16_0R5_3X3]  89.63 19.68 270 top
U33  STMPE1600QTR  [QFN24_0R5_4X4]  81.63 19.56 90 top
U34  ST1L05BPUR  [DFN6_0R95_3X3]  47.09 17.65 90 top
U35  -  [MP34DT01TR]  96.62 15.11 270 top
U36  -  [MP34DT01TR]  10.89 12.57 270 top
U37  ST890CDR  [SOIC8_1R27_4R9X6]  80.11 45.72 270 top
X1  NDK NX3215SA-32.768K-STD-MUA-14  [XTAL_2SM_3R2X1R5]  56.74 106.05 180 top
X2  8MHz (with socket)  [XTAL_SOCKET]  70.71 105.66 0 top
X3  8MHz  [XTAL_2SM_12R7X4R7]  53.82 50.16 90 top
Z1  SMAJ5.0A-TR  [SMA]  19.53 32.38 0 top

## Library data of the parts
B1 B2 = PB10
B3 = MT-008A
BT1 = BAT_2SM_CR1220
C1 C2 C4 C6 C9 C10 C13-C16 C21-C24 C27-C29 C32-C34 C46 C47 C53 C56-C58 C73 C80 C81 C102-C104 C108 C110 C112 C118 C120 C122 C125-C130 C138 = 0603C
C3 C5 C7 C8 C11 C12 C17-C20 C25 C26 C30 C31 C35 C36 C38-C45 C48-C52 C60-C66 C68-C70 C72 C74-C79 C82-C87 C90-C97 C101 C105 C106 C109 C111 C113 C114 C117 C119 C121 C123 C124 C132-C137 C139 C141-C145 = 0402C
C37 = 1206C
C54 C55 C88 C89 R1 R6 R8 R9 R14 R19-R22 R25-R29 R32 R37 R40-R42 R45 R51 R55 R57 R59 R60 R63 R67 R74 R79 R80 R100-R102 R110 R112 R114 R115 R117 R121 R122 R124 R125 R127-R130 R132-R134 R136-R139 R159 R161 R163-R173 R175-R187 R190 R193 R195 R196 R200 R211-R218 R224-R227 R229 R230 R232 R238 R239 R241-R251 R253-R264 R267 R268 = 0402R
C59 C67 C71 C99 C107 C115 C116 C140 = TAN-A
C98 C131 = 0805C
C100 = C310M-6
CN1 = MOLEX_47590001
CN2 = IDC34S
CN3 = SSM-104-L-DH
CN4 JP1 JP2 JP4 JP5 JP7 JP10 JP12 JP14 JP16 = SIP3
CN5 CN9 = DB9_M
CN6 CN7 = FTR-120-53-L-D-LC
CN8 CN10 JP3 JP6 JP8 JP9 JP13 JP18 JP19 = SIP2
CN11 CN14 = HDR_2X24_2R54
CN12 = FTSH-110-01-L-DV
CN13 = HDR_2X4_2R54_N
CN15 = IDC20S
CN16 = HDR_2X3-1_2R54-6
CN17 = USB-B
CN18 = MSD_PJS008_
CN19 = HDR_2X17_2R54
CN20 CN21 = PJ3028B
CN22 = PWR_JACK_DC10
CN23 = SAM_C816
D1 = BGA11_0R5_1R57X2R07
D2 = SOT23-213
D3-D8 = SOD-323
JP11 = SIP4
JP15 = HDR_2X3_2R54
JP17 = HDR_2X4_2R54
L1 L3 L4 = 0603L
L2 = BNX001
LD1-LD7 LD9 = 0603D
LD8 = LED2_3528
R2-R5 R7 R10-R13 R15-R18 R23 R24 R31 R34 R43 R44 R46 R58 R61 R69-R73 R75-R77 R87-R89 R92-R96 R105-R107 R111 R113 R116 R118-R120 R123 R126 R131 R135 R140-R158 R160 R162 R174 R188 R189 R191 R192 R194 R197-R199 R201-R210 R219-R223 R228 R231 R233-R237 R240 R252 R265 R266 = 0603R
R30 = HDR_1X2_1R27
R33 R35 R36 R38 R39 R48 R50 R53 R54 R56 R62 R64-R66 R68 R78 R81-R86 R90 R91 R97-R99 R103 R104 R108 R109 SB1-SB51 = SB_0603
R52 = PVT901
RS1 = RP0402X8_REV
RV1 RV3 = 3386P
RV2 = PTF_3314J
SW1 = SW1_3TH_2R54_10X2R5
T1 T4 T6 = SOT-23
T2 T3 = SOT23-6
TP1-TP18 = TP
TP19 = TP_C79
TS1 = TS_PAD
U1 U20 = SOT23-5
U2 = BGA48_0R75_9X11
U3 U4 = QFN16_0R65_4X4
U5 = BGA64_1_10X13
U6 = TSSOP8_0R65_3X6R4
U7 = TQFP144_0R5_22X22_SOCKET
U8 U37 = SOIC8_1R27_4R9X6
U9 = DFN8_1R27_6X8_TP4R8X5R8
U10 = SSOP28_0R65_10R2X7R8
U11 = IR_VISHAY3
U12 U24 U25 = USOP8_0R5_2X3R1
U13 U16 = SC70-5
U14 = TSSOP16_0R65_5X6R4
U15 = TSSOP14_0R65_5X6R4
U17-U19 = SOT-353
U21 U22 = TSSOP48_0R5_12R5X8R1
U23 = LQFP48_0R5_9X9
U26 U27 = SOT-223
U28 U34 = DFN6_0R95_3X3
U29 = BGA72_0R5_4R5X4
U30 = SOIC28W_1R27_17R9X10R325
U31 = TYCO_ZEN056V130A24LS
U32 = QFN16_0R5_3X3
U33 = QFN24_0R5_4X4
U35 U36 = MP34DT01TR
X1 = XTAL_2SM_3R2X1R5
X2 = XTAL_SOCKET
X3 = XTAL_2SM_12R7X4R7
Z1 = SMA

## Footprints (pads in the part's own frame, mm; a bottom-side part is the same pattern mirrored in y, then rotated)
0402C
  rect 0.559x0.559 smd: 1(-0.508,0) 2(0.508,0)
0402R
  rect 0.559x0.559 smd: 1(-0.508,0) 2(0.508,0)
0603C
  rect 0.889x0.813 smd: 1(-0.762,0) 2(0.762,0)
0603D
  rect 0.889x0.813 smd: 1(-0.762,0) 2(0.762,0)
0603L
  rect 0.889x0.813 smd: 1(-0.762,0) 2(0.762,0)
0603R
  rect 0.787x0.813 smd: 1(-0.762,0) 2(0.762,0)
0805C
  rect 1.143x1.27 smd: 1(-0.889,0) 2(0.889,0)
1206C
  rect 1.168x1.524 smd: 1(-1.473,0) 2(1.473,0)
3386P
  rect 1.168x1.168 hole 0.762: 1(-2.54,0)
  round 1.168 hole 0.762: 2(0,2.54) 3(2.54,0)
BAT_2SM_CR1220
  round 1.473 hole 1.473 unplated: (-3.75,0)
  round 1.194 hole 1.194 unplated: (3.75,0)
  rect 4.064x2.159 smd: 1(-7.95,0) 2(7.95,0)
BGA11_0R5_1R57X2R07
  round 0.249 smd: A2(0,0.75) A3(0.5,0.75) B1(-0.5,0.25) B2(0,0.25) B3(0.5,0.25) C1(-0.5,-0.25) C2(0,-0.25) C3(0.5,-0.25) D1(-0.5,-0.75) D2(0,-0.75) D3(0.5,-0.75)
BGA48_0R75_9X11
  round 0.356 smd: A1(-1.875,2.625) A2(-1.125,2.625) A3(-0.375,2.625) A4(0.375,2.625) A5(1.125,2.625) A6(1.875,2.625) B1(-1.875,1.875) B2(-1.125,1.875) B3(-0.375,1.875) B4(0.375,1.875) B5(1.125,1.875) B6(1.875,1.875) C1(-1.875,1.125) C2(-1.125,1.125) C3(-0.375,1.125) C4(0.375,1.125) C5(1.125,1.125) C6(1.875,1.125) D1(-1.875,0.375) D2(-1.125,0.375) D3(-0.375,0.375) D4(0.375,0.375) D5(1.125,0.375) D6(1.875,0.375) E1(-1.875,-0.375) E2(-1.125,-0.375) E3(-0.375,-0.375) E4(0.375,-0.375) E5(1.125,-0.375) E6(1.875,-0.375) F1(-1.875,-1.125) F2(-1.125,-1.125) F3(-0.375,-1.125) F4(0.375,-1.125) F5(1.125,-1.125) F6(1.875,-1.125) G1(-1.875,-1.875) G2(-1.125,-1.875) G3(-0.375,-1.875) G4(0.375,-1.875) G5(1.125,-1.875) G6(1.875,-1.875) H1(-1.875,-2.625) H2(-1.125,-2.625) H3(-0.375,-2.625) H4(0.375,-2.625) H5(1.125,-2.625) H6(1.875,-2.625)
BGA64_1_10X13
  round 0.457 smd: A1(-3.5,3.5) A2(-2.5,3.5) A3(-1.5,3.5) A4(-0.5,3.5) A5(0.5,3.5) A6(1.5,3.5) A7(2.5,3.5) A8(3.5,3.5) B1(-3.5,2.5) B2(-2.5,2.5) B3(-1.5,2.5) B4(-0.5,2.5) B5(0.5,2.5) B6(1.5,2.5) B7(2.5,2.5) B8(3.5,2.5) C1(-3.5,1.5) C2(-2.5,1.5) C3(-1.5,1.5) C4(-0.5,1.5) C5(0.5,1.5) C6(1.5,1.5) C7(2.5,1.5) C8(3.5,1.5) D1(-3.5,0.5) D2(-2.5,0.5) D3(-1.5,0.5) D4(-0.5,0.5) D5(0.5,0.5) D6(1.5,0.5) D7(2.5,0.5) D8(3.5,0.5) E1(-3.5,-0.5) E2(-2.5,-0.5) E3(-1.5,-0.5) E4(-0.5,-0.5) E5(0.5,-0.5) E6(1.5,-0.5) E7(2.5,-0.5) E8(3.5,-0.5) F1(-3.5,-1.5) F2(-2.5,-1.5) F3(-1.5,-1.5) F4(-0.5,-1.5) F5(0.5,-1.5) F6(1.5,-1.5) F7(2.5,-1.5) F8(3.5,-1.5) G1(-3.5,-2.5) G2(-2.5,-2.5) G3(-1.5,-2.5) G4(-0.5,-2.5) G5(0.5,-2.5) G6(1.5,-2.5) G7(2.5,-2.5) G8(3.5,-2.5) H1(-3.5,-3.5) H2(-2.5,-3.5) H3(-1.5,-3.5) H4(-0.5,-3.5) H5(0.5,-3.5) H6(1.5,-3.5) H7(2.5,-3.5) H8(3.5,-3.5)
BGA72_0R5_4R5X4
  round 0.249 smd: A1(-2,1.75) A2(-1.5,1.75) A3(-1,1.75) A4(-0.5,1.75) A5(0,1.75) A6(0.5,1.75) A7(1,1.75) A8(1.5,1.75) A9(2,1.75) B1(-2,1.25) B2(-1.5,1.25) B3(-1,1.25) B4(-0.5,1.25) B5(0,1.25) B6(0.5,1.25) B7(1,1.25) B8(1.5,1.25) B9(2,1.25) C1(-2,0.75) C2(-1.5,0.75) C3(-1,0.75) C4(-0.5,0.75) C5(0,0.75) C6(0.5,0.75) C7(1,0.75) C8(1.5,0.75) C9(2,0.75) D1(-2,0.25) D2(-1.5,0.25) D3(-1,0.25) D4(-0.5,0.25) D5(0,0.25) D6(0.5,0.25) D7(1,0.25) D8(1.5,0.25) D9(2,0.25) E1(-2,-0.25) E2(-1.5,-0.25) E3(-1,-0.25) E4(-0.5,-0.25) E5(0,-0.25) E6(0.5,-0.25) E7(1,-0.25) E8(1.5,-0.25) E9(2,-0.25) F1(-2,-0.75) F2(-1.5,-0.75) F3(-1,-0.75) F4(-0.5,-0.75) F5(0,-0.75) F6(0.5,-0.75) F7(1,-0.75) F8(1.5,-0.75) F9(2,-0.75) G1(-2,-1.25) G2(-1.5,-1.25) G3(-1,-1.25) G4(-0.5,-1.25) G5(0,-1.25) G6(0.5,-1.25) G7(1,-1.25) G8(1.5,-1.25) G9(2,-1.25) H1(-2,-1.75) H2(-1.5,-1.75) H3(-1,-1.75) H4(-0.5,-1.75) H5(0,-1.75) H6(0.5,-1.75) H7(1,-1.75) H8(1.5,-1.75) H9(2,-1.75)
BNX001
  round 1.981 hole 1.219: 1(2.5,2.5) 2(-2.5,2.5) 3(2.5,-2.5) 4(0,0) 5(5,0) 6(-2.5,-2.5)
C310M-6
  rect 5.08x3.048 smd: 1(3.175,0) 2(-3.175,0)
DB9_M
  rect 1.778x2.032 hole 0.965: 1(5.537,0)
  oval 1.778x2.032 hole 0.965: 2(2.769,0) 3(0,0) 4(-2.769,0) 5(-5.537,0) 6(4.166,2.794) 7(1.397,2.794) 8(-1.372,2.794) 9(-4.14,2.794)
  oval 4.572x2.286 hole 3.556x1.27: 10(-12.522,1.397) 11(12.522,1.397)
DFN6_0R95_3X3
  rect 0.457x0.711 smd: 1(-0.95,-1.436) 2(0,-1.436) 3(0.95,-1.436) 4(0.95,1.436) 5(0,1.436) 6(-0.95,1.436)
  rect 2.515x1.753 smd: 7(0,0)
DFN8_1R27_6X8_TP4R8X5R8
  rect 0.559x0.914 smd: 1(-1.905,-3.9) 2(-0.635,-3.9) 3(0.635,-3.9) 4(1.905,-3.9) 5(1.905,3.9) 6(0.635,3.9) 7(-0.635,3.9) 8(-1.905,3.9)
  rect 4.801x5.791 smd: 9(0,0)
FTR-120-53-L-D-LC
  round 1.194 hole 1.194 unplated: (-11.43,0) (11.43,0)
  rect 0.711x2.896 smd: 1(-12.065,-2.705) 2(-12.065,2.705) 3(-10.795,-2.705) 4(-10.795,2.705) 5(-9.525,-2.705) 6(-9.525,2.705) 7(-8.255,-2.705) 8(-8.255,2.705) 9(-6.985,-2.705) 10(-6.985,2.705) 11(-5.715,-2.705) 12(-5.715,2.705) 13(-4.445,-2.705) 14(-4.445,2.705) 15(-3.175,-2.705) 16(-3.175,2.705) 17(-1.905,-2.705) 18(-1.905,2.705) 19(-0.635,-2.705) 20(-0.635,2.705) 21(0.635,-2.705) 22(0.635,2.705) 23(1.905,-2.705) 24(1.905,2.705) 25(3.175,-2.705) 26(3.175,2.705) 27(4.445,-2.705) 28(4.445,2.705) 29(5.715,-2.705) 30(5.715,2.705) 31(6.985,-2.705) 32(6.985,2.705) 33(8.255,-2.705) 34(8.255,2.705) 35(9.525,-2.705) 36(9.525,2.705) 37(10.795,-2.705) 38(10.795,2.705) 39(12.065,-2.705) 40(12.065,2.705)
FTSH-110-01-L-DV
  round 0.965 hole 0.965 unplated: (-5.08,0) (5.08,0)
  rect 0.737x2.794 smd: 1(-5.715,-2.03) 2(-5.715,2.03) 3(-4.445,-2.03) 4(-4.445,2.03) 5(-3.175,-2.03) 6(-3.175,2.03) 7(-1.905,-2.03) 8(-1.905,2.03) 9(-0.635,-2.03) 10(-0.635,2.03) 11(0.635,-2.03) 12(0.635,2.03) 13(1.905,-2.03) 14(1.905,2.03) 15(3.175,-2.03) 16(3.175,2.03) 17(4.445,-2.03) 18(4.445,2.03) 19(5.715,-2.03) 20(5.715,2.03)
HDR_1X2_1R27
  rect 0.914x0.914 hole 0.635: 1(0,0)
  round 0.914 hole 0.635: 2(1.27,0)
HDR_2X3-1_2R54-6
  rect 1.524x1.524 hole 1.016: 1(0,0)
  round 1.524 hole 1.016: 2(0,2.54) 3(2.54,0) 4(2.54,2.54) 5(5.08,0)
HDR_2X3_2R54
  rect 1.321x1.321 hole 0.914: 1(0,0)
  round 1.321 hole 0.914: 2(0,2.54) 3(2.54,0) 4(2.54,2.54) 5(5.08,0) 6(5.08,2.54)
HDR_2X4_2R54
  rect 1.321x1.321 hole 0.914: 1(0,0)
  round 1.321 hole 0.914: 2(0,2.54) 3(2.54,0) 4(2.54,2.54) 5(5.08,0) 6(5.08,2.54) 7(7.62,0) 8(7.62,2.54)
HDR_2X4_2R54_N
  rect 1.321x1.321 hole 0.914: 1(0,0)
  round 1.321 hole 0.914: 2(0,-2.54) 3(2.54,0) 4(2.54,-2.54) 5(5.08,0) 6(5.08,-2.54) 7(7.62,0) 8(7.62,-2.54)
HDR_2X17_2R54
  rect 1.321x1.321 hole 0.914: 1(0,0)
  round 1.321 hole 0.914: 2(0,2.54) 3(2.54,0) 4(2.54,2.54) 5(5.08,0) 6(5.08,2.54) 7(7.62,0) 8(7.62,2.54) 9(10.16,0) 10(10.16,2.54) 11(12.7,0) 12(12.7,2.54) 13(15.24,0) 14(15.24,2.54) 15(17.78,0) 16(17.78,2.54) 17(20.32,0) 18(20.32,2.54) 19(22.86,0) 20(22.86,2.54) 21(25.4,0) 22(25.4,2.54) 23(27.94,0) 24(27.94,2.54) 25(30.48,0) 26(30.48,2.54) 27(33.02,0) 28(33.02,2.54) 29(35.56,0) 30(35.56,2.54) 31(38.1,0) 32(38.1,2.54) 33(40.64,0) 34(40.64,2.54)
HDR_2X24_2R54
  rect 1.321x1.321 hole 0.914: 1(0,0)
  round 1.321 hole 0.914: 2(0,2.54) 3(2.54,0) 4(2.54,2.54) 5(5.08,0) 6(5.08,2.54) 7(7.62,0) 8(7.62,2.54) 9(10.16,0) 10(10.16,2.54) 11(12.7,0) 12(12.7,2.54) 13(15.24,0) 14(15.24,2.54) 15(17.78,0) 16(17.78,2.54) 17(20.32,0) 18(20.32,2.54) 19(22.86,0) 20(22.86,2.54) 21(25.4,0) 22(25.4,2.54) 23(27.94,0) 24(27.94,2.54) 25(30.48,0) 26(30.48,2.54) 27(33.02,0) 28(33.02,2.54) 29(35.56,0) 30(35.56,2.54) 31(38.1,0) 32(38.1,2.54) 33(40.64,0) 34(40.64,2.54) 35(43.18,0) 36(43.18,2.54) 37(45.72,0) 38(45.72,2.54) 39(48.26,0) 40(48.26,2.54) 41(50.8,0) 42(50.8,2.54) 43(53.34,0) 44(53.34,2.54) 45(55.88,0) 46(55.88,2.54) 47(58.42,0) 48(58.42,2.54)
IDC20S
  round 1.524 hole 1.016: 1(0,0) 2(2.54,0) 3(0,-2.54) 4(2.54,-2.54) 5(0,-5.08) 6(2.54,-5.08) 7(0,-7.62) 8(2.54,-7.62) 9(0,-10.16) 10(2.54,-10.16) 11(0,-12.7) 12(2.54,-12.7) 13(0,-15.24) 14(2.54,-15.24) 15(0,-17.78) 16(2.54,-17.78) 17(0,-20.32) 18(2.54,-20.32) 19(0,-22.86) 20(2.54,-22.86)
IDC34S
  rect 1.524x1.524 hole 1.016: 1(0,0)
  round 1.524 hole 1.016: 2(2.54,0) 3(0,-2.54) 4(2.54,-2.54) 5(0,-5.08) 6(2.54,-5.08) 7(0,-7.62) 8(2.54,-7.62) 9(0,-10.16) 10(2.54,-10.16) 11(0,-12.7) 12(2.54,-12.7) 13(0,-15.24) 14(2.54,-15.24) 15(0,-17.78) 16(2.54,-17.78) 17(0,-20.32) 18(2.54,-20.32) 19(0,-22.86) 20(2.54,-22.86) 21(0,-25.4) 22(2.54,-25.4) 23(0,-27.94) 24(2.54,-27.94) 25(0,-30.48) 26(2.54,-30.48) 27(0,-33.02) 28(2.54,-33.02) 29(0,-35.56) 30(2.54,-35.56) 31(0,-38.1) 32(2.54,-38.1) 33(0,-40.64) 34(2.54,-40.64)
IR_VISHAY3
  rect 0.711x1.397 smd: 1(3.325,0) 2(2.375,0) 3(1.425,0) 4(0.475,0) 5(-0.475,0) 6(-1.425,0) 7(-2.375,0) 8(-3.325,0)
LED2_3528
  rect 1.118x1.499 smd: 1(-0.75,-1.5) 2(-0.75,1.5) 3(0.75,1.5) 4(0.75,-1.5)
LQFP48_0R5_9X9
  rect 1.346x0.279 smd: 1(-4.35,2.75) 2(-4.35,2.25) 3(-4.35,1.75) 4(-4.35,1.25) 5(-4.35,0.75) 6(-4.35,0.25) 7(-4.35,-0.25) 8(-4.35,-0.75) 9(-4.35,-1.25) 10(-4.35,-1.75) 11(-4.35,-2.25) 12(-4.35,-2.75) 25(4.35,-2.75) 26(4.35,-2.25) 27(4.35,-1.75) 28(4.35,-1.25) 29(4.35,-0.75) 30(4.35,-0.25) 31(4.35,0.25) 32(4.35,0.75) 33(4.35,1.25) 34(4.35,1.75) 35(4.35,2.25) 36(4.35,2.75)
  rect 0.279x1.346 smd: 13(-2.75,-4.35) 14(-2.25,-4.35) 15(-1.75,-4.35) 16(-1.25,-4.35) 17(-0.75,-4.35) 18(-0.25,-4.35) 19(0.25,-4.35) 20(0.75,-4.35) 21(1.25,-4.35) 22(1.75,-4.35) 23(2.25,-4.35) 24(2.75,-4.35) 37(2.75,4.35) 38(2.25,4.35) 39(1.75,4.35) 40(1.25,4.35) 41(0.75,4.35) 42(0.25,4.35) 43(-0.25,4.35) 44(-0.75,4.35) 45(-1.25,4.35) 46(-1.75,4.35) 47(-2.25,4.35) 48(-2.75,4.35)
MOLEX_47590001
  rect 0.406x1.346 smd: 1(1.3,0) 2(0.65,0) 3(0,0) 4(-0.65,0) 5(-1.3,0)
  oval 1.067x1.6 hole 0.762x0.838: 6(2.275,0.325) 7(-2.275,0.325)
  oval 1.397x1.905 hole 0.838x1.499: 8(-4.15,-2.855) 9(4.15,-2.855)
  rect 2.896x2.007 smd: 10(0,-2.675)
MP34DT01TR
  rect 0.508x1.067 smd: 1(-0.425,0.675) 2(-0.425,-0.675) 3(0.425,-0.675) 4(0.425,0.675)
  round 0.152 smd: 5(-0.025,-1.753)
MSD_PJS008_
  round 0.711 hole 0.711 unplated: (0,0) (7.55,0)
  rect 0.813x1.6 smd: 1(1.475,5.8) 2(2.575,5.8) 3(3.675,5.8) 4(4.775,5.8) 5(5.875,5.8) 6(6.975,5.8) 7(8.075,5.8) 8(9.175,5.8)
  rect 0.838x1.6 smd: 9(10.325,5.8)
  rect 1.956x1.905 smd: 10(11.225,-4.4)
  rect 1.524x3.073 smd: 11(11.45,-7.35)
  rect 1.397x3.429 smd: 12(-3.503,-7.357)
  rect 1.6x3.505 smd: 13(-3.4,3.65)
  rect 1.194x3.099 smd: 14(11.6,4.15)
MT-008A
  round 0.711 hole 0.711 unplated: (-1.9,0)
  round 0.991 hole 0.991 unplated: (1.9,0)
  rect 1.016x1.778 smd: 1(-1.4,-3.1) 2(0,-3.1) 3(1.4,-3.1) 4(1.4,3.1) 5(0,3.1) 6(-1.4,3.1) 7(-3.6,0) 8(3.7,0)
PB10
  rect 1.524x1.016 smd: 1(-4.5,-2.223) 2(-4.5,2.223) 3(4.5,2.223) 4(4.5,-2.223)
PJ3028B
  round 2.007 hole 2.007 unplated: (0,0) (7,0)
  rect 1.219x2.489 smd: 2(-3.9,-4) 7(-2,4)
  rect 2.007x2.489 smd: 3(-1,-4) 4(0.8,4) 6(8.2,-4)
  rect 2.489x2.007 smd: 5(12.25,0.8)
PTF_3314J
  rect 1.295x2.007 smd: 1(1.15,-2) 3(-1.15,-2)
  rect 2.007x2.007 smd: 2(0,2)
PVT901
  round 1.524 hole 0.762: 1(0,1.27) 2(0,-1.27)
PWR_JACK_DC10
  rect 2.032x4.216 hole 1.016x3.2: 1(0,0)
  oval 4.216x2.032 hole 3.2x1.016: 2(-3.1,-5)
  oval 2.032x4.216 hole 1.016x3.2: 3(-6.2,0)
QFN16_0R5_3X3
  oval 0.813x0.279 smd: 1(-1.487,0.75) 2(-1.487,0.25) 3(-1.487,-0.25) 4(-1.487,-0.75) 9(1.487,-0.75) 10(1.487,-0.25) 11(1.487,0.25) 12(1.487,0.75)
  oval 0.279x0.813 smd: 5(-0.75,-1.487) 6(-0.25,-1.487) 7(0.25,-1.487) 8(0.75,-1.487) 13(0.75,1.487) 14(0.25,1.487) 15(-0.25,1.487) 16(-0.75,1.487)
  rect 1.524x1.524 smd: 17(0,0)
QFN16_0R65_4X4
  oval 0.762x0.279 smd: 1(-1.95,0.975) 2(-1.95,0.325) 3(-1.95,-0.325) 4(-1.95,-0.975) 9(1.95,-0.975) 10(1.95,-0.325) 11(1.95,0.325) 12(1.95,0.975)
  oval 0.279x0.762 smd: 5(-0.975,-1.95) 6(-0.325,-1.95) 7(0.325,-1.95) 8(0.975,-1.95) 13(0.975,1.95) 14(0.325,1.95) 15(-0.325,1.95) 16(-0.975,1.95)
  rect 2.642x2.642 smd: 17(0,0)
QFN24_0R5_4X4
  oval 0.711x0.279 smd: 1(-1.95,1.25) 2(-1.95,0.75) 3(-1.95,0.25) 4(-1.95,-0.25) 5(-1.95,-0.75) 6(-1.95,-1.25) 13(1.95,-1.25) 14(1.95,-0.75) 15(1.95,-0.25) 16(1.95,0.25) 17(1.95,0.75) 18(1.95,1.25)
  oval 0.279x0.711 smd: 7(-1.25,-1.95) 8(-0.75,-1.95) 9(-0.25,-1.95) 10(0.25,-1.95) 11(0.75,-1.95) 12(1.25,-1.95) 19(1.25,1.95) 20(0.75,1.95) 21(0.25,1.95) 22(-0.25,1.95) 23(-0.75,1.95) 24(-1.25,1.95)
  rect 2.692x2.692 smd: 25(0,0)
RP0402X8_REV
  rect 0.406x0.762 smd: 1(-1.941,-0.777) 2(-1.941,0.523) 15(1.687,-0.777) 16(1.687,0.523)
  rect 0.279x0.762 smd: 3(-1.377,-0.777) 4(-1.377,0.523) 5(-0.877,-0.777) 6(-0.877,0.523) 7(-0.377,-0.777) 8(-0.377,0.523) 9(0.123,-0.777) 10(0.123,0.523) 11(0.623,-0.777) 12(0.623,0.523) 13(1.123,-0.777) 14(1.123,0.523)
SAM_C816
  round 2.21 hole 2.21 unplated: (-10.16,26.67) (10.16,-17.78)
  rect 1.499x1.295 smd: 1(-12.3,-3.81) 2(-12.3,-1.27) 3(-12.3,1.27) 4(-12.3,3.81) 5(12.3,-3.81) 6(12.3,-1.27) 7(12.3,1.27) 8(12.3,3.81)
  rect 1.753x0.991 smd: 17(-5.5,8.89) 18(-5.5,11.43)
SB_0603
  round 0.152 smd: 1(-0.762,0) 2(0.762,0)
SC70-5
  rect 0.356x0.94 smd: 1(-0.65,-0.92) 2(0,-0.92) 3(0.65,-0.92) 4(0.65,0.92) 5(-0.65,0.92)
SIP2
  round 1.524 hole 1.016: 1(0,0) 2(2.54,0)
SIP3
  rect 1.524x1.524 hole 1.016: 1(0,0)
  round 1.524 hole 1.016: 2(2.54,0) 3(5.08,0)
SIP4
  rect 1.321x1.321 hole 0.914: 1(0,0)
  round 1.321 hole 0.914: 2(2.54,0) 3(5.08,0) 4(7.62,0)
SMA
  rect 2.007x1.676 smd: 1(-1.9,0) 2(1.9,0)
SOD-323
  rect 0.813x0.813 smd: 1(-1.125,0) 2(1.125,0)
SOIC8_1R27_4R9X6
  rect 0.559x1.778 smd: 1(-1.905,-2.624) 2(-0.635,-2.624) 3(0.635,-2.624) 4(1.905,-2.624) 5(1.905,2.624) 6(0.635,2.624) 7(-0.635,2.624) 8(-1.905,2.624)
SOIC28W_1R27_17R9X10R325
  rect 0.584x1.956 smd: 1(-8.255,-4.795) 2(-6.985,-4.795) 3(-5.715,-4.795) 4(-4.445,-4.795) 5(-3.175,-4.795) 6(-1.905,-4.795) 7(-0.635,-4.795) 8(0.635,-4.795) 9(1.905,-4.795) 10(3.175,-4.795) 11(4.445,-4.795) 12(5.715,-4.795) 13(6.985,-4.795) 14(8.255,-4.795) 15(8.255,4.795) 16(6.985,4.795) 17(5.715,4.795) 18(4.445,4.795) 19(3.175,4.795) 20(1.905,4.795) 21(0.635,4.795) 22(-0.635,4.795) 23(-1.905,4.795) 24(-3.175,4.795) 25(-4.445,4.795) 26(-5.715,4.795) 27(-6.985,4.795) 28(-8.255,4.795)
SOT23-5
  rect 0.635x1.143 smd: 1(-0.95,-1.2) 2(0,-1.2) 3(0.95,-1.2) 4(0.95,1.2) 5(-0.95,1.2)
SOT23-6
  rect 0.635x1.346 smd: 1(-0.95,-1.2) 2(0,-1.2) 3(0.95,-1.2) 4(0.95,1.2) 5(0,1.2) 6(-0.95,1.2)
SOT23-213
  rect 0.635x1.143 smd: 1(0.95,-1.1) 2(-0.95,-1.1) 3(0,1.1)
SOT-23
  rect 0.635x1.143 smd: 1(-0.95,-1.1) 2(0.95,-1.1) 3(0,1.1)
SOT-223
  rect 1.016x1.803 smd: 1(-2.3,-3.15) 2(0,-3.15) 3(2.3,-3.15)
  rect 3.302x1.803 smd: 4(0,3.15)
SOT-353
  rect 0.457x1.245 smd: 1(-0.65,-0.9) 2(0,-0.9) 3(0.65,-0.9) 4(0.65,0.9) 5(-0.65,0.9)
SSM-104-L-DH
  round 1.194 hole 1.194 unplated: (-2.54,0) (2.54,0)
  rect 1.016x2.286 smd: 1(3.81,-4.698) 2(3.81,4.698) 3(1.27,-4.698) 4(1.27,4.698) 5(-1.27,-4.698) 6(-1.27,4.698) 7(-3.81,-4.698) 8(-3.81,4.698)
SSOP28_0R65_10R2X7R8
  rect 0.356x1.753 smd: 1(-4.225,-3.55) 2(-3.575,-3.55) 3(-2.925,-3.55) 4(-2.275,-3.55) 5(-1.625,-3.55) 6(-0.975,-3.55) 7(-0.325,-3.55) 8(0.325,-3.55) 9(0.975,-3.55) 10(1.625,-3.55) 11(2.275,-3.55) 12(2.925,-3.55) 13(3.575,-3.55) 14(4.225,-3.55) 15(4.225,3.55) 16(3.575,3.55) 17(2.925,3.55) 18(2.275,3.55) 19(1.625,3.55) 20(0.975,3.55) 21(0.325,3.55) 22(-0.325,3.55) 23(-0.975,3.55) 24(-1.625,3.55) 25(-2.275,3.55) 26(-2.925,3.55) 27(-3.575,3.55) 28(-4.225,3.55)
SW1_3TH_2R54_10X2R5
  rect 1.422x1.422 hole 1.016: 1(0,0)
  round 1.422 hole 1.016: 2(2.54,0) 3(5.08,0)
TAN-A
  rect 1.27x1.524 smd: 1(1.397,0) 2(-1.397,0)
TP
  round 1.524 hole 1.016: 1(0,0)
TP_C79
  round 2.007 smd: 1(0,0)
TQFP144_0R5_22X22_SOCKET
  round 1.499 hole 1.499 unplated: (-8.001,0) (8.001,0)
  rect 1.524x0.279 smd: 1(-10.8,8.75) 2(-10.8,8.25) 3(-10.8,7.75) 4(-10.8,7.249) 5(-10.8,6.749) 6(-10.8,6.251) 7(-10.8,5.751) 8(-10.8,5.25) 9(-10.8,4.75) 10(-10.8,4.249) 11(-10.8,3.749) 12(-10.8,3.251) 13(-10.8,2.751) 14(-10.8,2.25) 15(-10.8,1.75) 16(-10.8,1.25) 17(-10.8,0.749) 18(-10.8,0.249) 19(-10.8,-0.249) 20(-10.8,-0.749) 21(-10.8,-1.25) 22(-10.8,-1.75) 23(-10.8,-2.25) 24(-10.8,-2.751) 25(-10.8,-3.251) 26(-10.8,-3.749) 27(-10.8,-4.249) 28(-10.8,-4.75) 29(-10.8,-5.25) 30(-10.8,-5.751) 31(-10.8,-6.251) 32(-10.8,-6.749) 33(-10.8,-7.249) 34(-10.8,-7.75) 35(-10.8,-8.25) 36(-10.8,-8.75) 73(10.8,-8.75) 74(10.8,-8.25) 75(10.8,-7.75) 76(10.8,-7.249) 77(10.8,-6.749) 78(10.8,-6.251) 79(10.8,-5.751) 80(10.8,-5.25) 81(10.8,-4.75) 82(10.8,-4.249) 83(10.8,-3.749) 84(10.8,-3.251) 85(10.8,-2.751) 86(10.8,-2.25) 87(10.8,-1.75) 88(10.8,-1.25) 89(10.8,-0.749) 90(10.8,-0.249) 91(10.8,0.249) 92(10.8,0.749) 93(10.8,1.25) 94(10.8,1.75) 95(10.8,2.25) 96(10.8,2.751) 97(10.8,3.251) 98(10.8,3.749) 99(10.8,4.249) 100(10.8,4.75) 101(10.8,5.25) 102(10.8,5.751) 103(10.8,6.251) 104(10.8,6.749) 105(10.8,7.249) 106(10.8,7.75) 107(10.8,8.25) 108(10.8,8.75)
  rect 0.279x1.524 smd: 37(-8.75,-10.8) 38(-8.25,-10.8) 39(-7.75,-10.8) 40(-7.249,-10.8) 41(-6.749,-10.8) 42(-6.251,-10.8) 43(-5.751,-10.8) 44(-5.25,-10.8) 45(-4.75,-10.8) 46(-4.249,-10.8) 47(-3.749,-10.8) 48(-3.251,-10.8) 49(-2.751,-10.8) 50(-2.25,-10.8) 51(-1.75,-10.8) 52(-1.25,-10.8) 53(-0.749,-10.8) 54(-0.249,-10.8) 55(0.249,-10.8) 56(0.749,-10.8) 57(1.25,-10.8) 58(1.75,-10.8) 59(2.25,-10.8) 60(2.751,-10.8) 61(3.251,-10.8) 62(3.749,-10.8) 63(4.249,-10.8) 64(4.75,-10.8) 65(5.25,-10.8) 66(5.751,-10.8) 67(6.251,-10.8) 68(6.749,-10.8) 69(7.249,-10.8) 70(7.75,-10.8) 71(8.25,-10.8) 72(8.75,-10.8) 109(8.75,10.8) 110(8.25,10.8) 111(7.75,10.8) 112(7.249,10.8) 113(6.749,10.8) 114(6.251,10.8) 115(5.751,10.8) 116(5.25,10.8) 117(4.75,10.8) 118(4.249,10.8) 119(3.749,10.8) 120(3.251,10.8) 121(2.751,10.8) 122(2.25,10.8) 123(1.75,10.8) 124(1.25,10.8) 125(0.749,10.8) 126(0.249,10.8) 127(-0.249,10.8) 128(-0.749,10.8) 129(-1.25,10.8) 130(-1.75,10.8) 131(-2.25,10.8) 132(-2.751,10.8) 133(-3.251,10.8) 134(-3.749,10.8) 135(-4.249,10.8) 136(-4.75,10.8) 137(-5.25,10.8) 138(-5.751,10.8) 139(-6.251,10.8) 140(-6.749,10.8) 141(-7.249,10.8) 142(-7.75,10.8) 143(-8.25,10.8) 144(-8.75,10.8)
  rect 0.991x2.489 smd rot 135: 145(-10.96,10.96) 147(10.96,-10.96)
  rect 0.991x2.489 smd rot 45: 146(-10.96,-10.96) 148(10.96,10.96)
TS_PAD
  round 10.008 smd: 1(0,0)
TSSOP8_0R65_3X6R4
  rect 0.356x1.524 smd: 1(-0.975,-3) 2(-0.325,-3) 3(0.325,-3) 4(0.975,-3) 5(0.975,3) 6(0.325,3) 7(-0.325,3) 8(-0.975,3)
TSSOP14_0R65_5X6R4
  rect 0.356x1.524 smd: 1(-1.95,-2.95) 2(-1.3,-2.95) 3(-0.65,-2.95) 4(0,-2.95) 5(0.65,-2.95) 6(1.3,-2.95) 7(1.95,-2.95) 8(1.95,2.95) 9(1.3,2.95) 10(0.65,2.95) 11(0,2.95) 12(-0.65,2.95) 13(-1.3,2.95) 14(-1.95,2.95)
TSSOP16_0R65_5X6R4
  rect 0.356x1.524 smd: 1(-2.275,-2.95) 2(-1.625,-2.95) 3(-0.975,-2.95) 4(-0.325,-2.95) 5(0.325,-2.95) 6(0.975,-2.95) 7(1.625,-2.95) 8(2.275,-2.95) 9(2.275,2.95) 10(1.625,2.95) 11(0.975,2.95) 12(0.325,2.95) 13(-0.325,2.95) 14(-0.975,2.95) 15(-1.625,2.95) 16(-2.275,2.95)
TSSOP48_0R5_12R5X8R1
  rect 0.279x1.524 smd: 1(-5.75,-3.787) 2(-5.25,-3.787) 3(-4.75,-3.787) 4(-4.25,-3.787) 5(-3.75,-3.787) 6(-3.25,-3.787) 7(-2.75,-3.787) 8(-2.25,-3.787) 9(-1.75,-3.787) 10(-1.25,-3.787) 11(-0.75,-3.787) 12(-0.25,-3.787) 13(0.25,-3.787) 14(0.75,-3.787) 15(1.25,-3.787) 16(1.75,-3.787) 17(2.25,-3.787) 18(2.75,-3.787) 19(3.25,-3.787) 20(3.75,-3.787) 21(4.25,-3.787) 22(4.75,-3.787) 23(5.25,-3.787) 24(5.75,-3.787) 25(5.75,3.787) 26(5.25,3.787) 27(4.75,3.787) 28(4.25,3.787) 29(3.75,3.787) 30(3.25,3.787) 31(2.75,3.787) 32(2.25,3.787) 33(1.75,3.787) 34(1.25,3.787) 35(0.75,3.787) 36(0.25,3.787) 37(-0.25,3.787) 38(-0.75,3.787) 39(-1.25,3.787) 40(-1.75,3.787) 41(-2.25,3.787) 42(-2.75,3.787) 43(-3.25,3.787) 44(-3.75,3.787) 45(-4.25,3.787) 46(-4.75,3.787) 47(-5.25,3.787) 48(-5.75,3.787)
TYCO_ZEN056V130A24LS
  rect 0.61x2.21 smd: 1(-1.745,0)
  rect 0.61x0.94 smd: 2(1.745,0.635) 3(1.745,-0.635)
unnamed
  round 3.505 hole 3.505 unplated: (0,0)
USB-B
  rect 1.27x1.27 hole 0.762: 1(0,0)
  round 1.27 hole 0.762: 2(-2.489,0) 3(-2.489,-2.032) 4(0,-2.032)
  round 3.175 hole 2.413: 5(-7.391,-4.699) 6(4.801,-4.699)
USOP8_0R5_2X3R1
  rect 0.279x0.711 smd: 1(-0.75,-1.5) 2(-0.25,-1.5) 3(0.25,-1.5) 4(0.75,-1.5) 5(0.75,1.5) 6(0.25,1.5) 7(-0.25,1.5) 8(-0.75,1.5)
XTAL_2SM_3R2X1R5
  rect 1.295x1.6 smd: 1(-1.15,0) 2(1.15,0)
XTAL_2SM_12R7X4R7
  rect 5.486x1.499 smd: 1(-4.25,0) 2(4.25,0)
